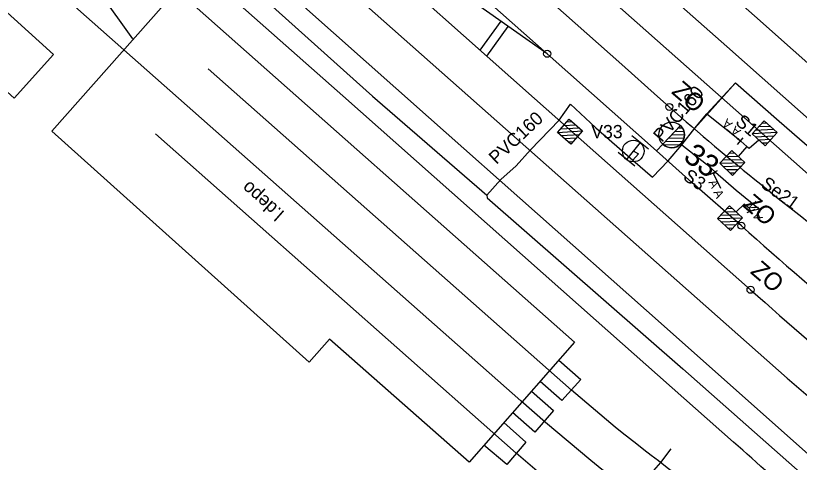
# Model space of a CAD drawing. Extents: x -496570 to -495506, y -1089156 to -1088046.
# Drawn here: x -496185.7 to -496096.7, y -1088542 to -1088491.2 of the extents above; entities that cross this region are included whole.
import ezdxf

# ---------------------------------------------------------------- set-up
doc = ezdxf.new("R2010")
doc.units = 0
for name, color, linetype in [('11', 7, 'Continuous'), ('14', 7, 'Continuous'), ('15', 7, 'Continuous'), ('20', 7, 'Continuous'), ('27', 7, 'Continuous'), ('39', 7, 'Continuous'), ('49', 7, 'Continuous'), ('54', 7, 'Continuous'), ('PŮVODNÍ_NÁVRH', 7, 'Continuous')]:
    doc.layers.add(name, color=color, linetype=linetype)

msp = doc.modelspace()

# ---------------------------------------------------------------- linework, layer by layer
at = {"layer": '11'}
for points in [[(-496132.942, -1088495.161), (-496130.564, -1088491.871)], [(-496132.204, -1088495.847), (-496129.754, -1088492.457)]]:
    msp.add_lwpolyline(points, dxfattribs=at)
at = {"layer": '14'}
for points in [[(-496500.326, -1088150.883), (-496478.319, -1088170.391), (-496459.205, -1088187.309), (-496440.603, -1088203.768), (-496419.398, -1088222.532), (-496401.337, -1088238.524), (-496381.863, -1088255.763), (-496363.496, -1088272.022), (-496344.908, -1088288.479), (-496325.602, -1088305.577), (-496305.115, -1088323.698), (-496285.279, -1088341.274), (-496267.778, -1088356.78), (-496248.642, -1088373.733), (-496220.391, -1088398.759), (-496201.351, -1088415.62), (-496182.974, -1088431.889), (-496164.259, -1088448.462), (-496145.687, -1088464.902), (-496132.984, -1088476.226), (-496115.09, -1088492.058), (-496092.682, -1088511.89), (-496073.961, -1088528.378)], [(-496111.45, -1088501.61), (-496112.796, -1088500.414), (-496116.847, -1088496.777), (-496137.726, -1088478.277), (-496158.004, -1088460.314), (-496179.39, -1088441.364), (-496198.571, -1088424.361), (-496223.52, -1088402.267), (-496247.329, -1088381.198), (-496269.626, -1088361.454), (-496288.304, -1088344.927), (-496319.947, -1088316.905), (-496344.485, -1088295.207), (-496348.139, -1088291.966), (-496366.841, -1088275.405), (-496385.169, -1088259.187), (-496404.395, -1088242.153), (-496422.154, -1088226.434), (-496443.818, -1088207.26), (-496462.548, -1088190.678), (-496481.576, -1088173.849), (-496503.417, -1088154.088)], [(-496036.118, -1088555.5), (-496048.975, -1088544.1), (-496066.196, -1088528.906), (-496086.152, -1088511.349), (-496104.929, -1088494.746), (-496123.588, -1088478.229), (-496142.293, -1088461.701), (-496160.965, -1088445.175), (-496179.891, -1088428.396), (-496198.214, -1088412.189), (-496217.292, -1088395.311), (-496245.811, -1088370.064), (-496264.918, -1088353.145), (-496281.988, -1088338.018), (-496302.247, -1088320.079), (-496322.57, -1088302.076), (-496341.966, -1088284.907), (-496360.552, -1088268.447), (-496378.713, -1088252.378), (-496398.4, -1088234.928), (-496416.447, -1088218.945), (-496437.668, -1088200.162), (-496456.103, -1088183.845), (-496474.042, -1088168.071)], [(-496419.776, -1088210.17), (-496413.73, -1088215.561), (-496395.384, -1088231.799), (-496375.938, -1088249.024), (-496357.661, -1088265.193), (-496339.088, -1088281.642), (-496320.817, -1088297.785), (-496278.447, -1088335.251), (-496262.212, -1088349.594), (-496242.734, -1088366.795), (-496214.147, -1088392.048), (-496195.339, -1088408.643), (-496176.8, -1088425.002), (-496157.997, -1088441.59), (-496139.148, -1088458.239), (-496120.509, -1088474.69), (-496101.775, -1088491.246), (-496088.913, -1088502.664), (-496081.326, -1088509.353), (-496072.768, -1088516.905)], [(-496183.115, -1088457.032), (-496166.27, -1088472.019), (-496131.046, -1088503.215), (-496098.048, -1088532.397), (-496093.805, -1088536.044)], [(-496093.621, -1088542.853), (-496114.06, -1088524.717), (-496138.8, -1088502.766), (-496174.593, -1088471.013)], [(-496173.425, -1088495.115), (-496178.653, -1088490.5), (-496194.892, -1088476.055)], [(-496147.947, -1088481.853), (-496126.772, -1088500.653), (-496102.22, -1088522.373)], [(-496104.138, -1088539.66), (-496119.75, -1088525.847), (-496148.539, -1088500.347), (-496166.679, -1088484.292)], [(-496128.341, -1088534.994), (-496173.425, -1088495.115)], [(-496125.191, -1088531.455), (-496163.844, -1088497.265)], [(-496131.495, -1088538.579), (-496169.855, -1088504.648)], [(-496103.261, -1088515.098), (-496108.88, -1088510.183), (-496112.903, -1088506.6)], [(-496117.617, -1088537.987), (-496122.554, -1088533.775), (-496125.191, -1088531.455)], [(-496120.36, -1088541.773), (-496125.528, -1088537.441), (-496128.341, -1088534.994)], [(-496084.463, -1088574.911), (-496099.443, -1088563.786), (-496104.369, -1088560.115), (-496107.079, -1088558.115), (-496114.808, -1088552.356), (-496123.542, -1088545.463), (-496128.839, -1088540.929), (-496131.495, -1088538.579)]]:
    msp.add_lwpolyline(points, dxfattribs=at)
for centre in [(-496111.45, -1088501.61), (-496103.261, -1088515.098), (-496102.22, -1088522.373)]:
    msp.add_circle(centre, 0.4, dxfattribs=at)
for centre, major_axis, ratio, start_param, end_param in [((-495904.217, -1088267.163), (240.608, -200.87), 0.998317, 4.684202, 4.771008), ((-495616.903, -1087969.14), (-563.673, 468.202), 0.997828, 1.536282, 1.586227), ((-495661.207, -1088025.176), (-508.889, 430.705), 0.996869, 1.547662, 1.600405)]:
    msp.add_ellipse(centre, major_axis=major_axis, ratio=ratio, start_param=start_param, end_param=end_param, dxfattribs=at)
for points in [[(-496060.305, -1088494.392), (-496069.107, -1088478.342), (-496082.819, -1088457.845), (-496098.833, -1088439.695), (-496101.304, -1088437.234), (-496120.979, -1088419.513)], [(-496076.529, -1088566.028), (-496092.943, -1088555.668), (-496104.359, -1088548.012), (-496117.617, -1088537.987)], [(-496076.075, -1088564.025), (-496087.586, -1088554.298), (-496104.138, -1088539.66)], [(-496063.641, -1088579.453), (-496076.368, -1088572.308), (-496088.307, -1088565.016), (-496095.758, -1088560.128), (-496107.252, -1088552.116), (-496120.36, -1088541.773)]]:
    msp.add_spline(points, degree=3, dxfattribs=at)
at = {"layer": '15'}
for p, q in [((-496123.441, -1088503.711), (-496122.116, -1088503.63)), ((-496123.09, -1088503.314), (-496122.513, -1088503.278)), ((-496099.993, -1088503.816), (-496101.319, -1088503.882)), ((-496100.386, -1088503.461), (-496100.964, -1088503.489)), ((-496124.144, -1088504.505), (-496121.321, -1088504.333)), ((-496123.793, -1088504.108), (-496121.718, -1088503.981)), ((-496123.747, -1088504.856), (-496121.672, -1088504.73)), ((-496099.206, -1088504.528), (-496102.031, -1088504.669)), ((-496099.599, -1088504.173), (-496101.676, -1088504.276)), ((-496123.35, -1088505.208), (-496122.024, -1088505.127)), ((-496122.953, -1088505.559), (-496122.375, -1088505.524)), ((-496114.768, -1088505.65), (-496116.312, -1088507.57)), ((-496113.808, -1088506.422), (-496115.728, -1088504.878)), ((-496099.562, -1088504.921), (-496101.638, -1088505.025)), ((-496099.918, -1088505.315), (-496101.245, -1088505.381)), ((-496100.274, -1088505.708), (-496100.852, -1088505.737)), ((-496115.352, -1088508.342), (-496117.272, -1088506.798)), ((-496104.982, -1088507.233), (-496103.654, -1088507.198)), ((-496104.617, -1088506.848), (-496104.039, -1088506.833)), ((-496105.712, -1088508.003), (-496102.885, -1088507.928)), ((-496105.347, -1088507.618), (-496103.269, -1088507.563)), ((-496105.328, -1088508.367), (-496103.249, -1088508.313)), ((-496104.942, -1088508.733), (-496103.615, -1088508.698)), ((-496104.558, -1088509.098), (-496103.98, -1088509.082)), ((-496105.242, -1088513.516), (-496103.915, -1088513.468)), ((-496104.881, -1088513.128), (-496104.303, -1088513.107)), ((-496105.965, -1088514.293), (-496103.138, -1088514.191)), ((-496105.604, -1088513.905), (-496103.526, -1088513.83)), ((-496105.577, -1088514.654), (-496103.499, -1088514.579)), ((-496105.188, -1088515.015), (-496103.861, -1088514.968)), ((-496104.8, -1088515.377), (-496104.222, -1088515.356))]:
    msp.add_line(p, q, dxfattribs=at)
for points in [[(-496122.819, -1088503.007), (-496121.321, -1088504.333), (-496122.646, -1088505.83), (-496124.144, -1088504.505)], [(-496122.819, -1088503.007), (-496121.321, -1088504.333), (-496122.646, -1088505.83), (-496124.144, -1088504.505)], [(-496100.549, -1088506.011), (-496102.031, -1088504.669), (-496100.689, -1088503.186), (-496099.206, -1088504.528)], [(-496100.549, -1088506.011), (-496102.031, -1088504.669), (-496100.689, -1088503.186), (-496099.206, -1088504.528)], [(-496104.335, -1088506.552), (-496102.885, -1088507.928), (-496104.261, -1088509.379), (-496105.712, -1088508.003)], [(-496104.335, -1088506.552), (-496102.885, -1088507.928), (-496104.261, -1088509.379), (-496105.712, -1088508.003)], [(-496104.602, -1088512.829), (-496103.138, -1088514.191), (-496104.501, -1088515.655), (-496105.965, -1088514.293)], [(-496104.602, -1088512.829), (-496103.138, -1088514.191), (-496104.501, -1088515.655), (-496105.965, -1088514.293)]]:
    msp.add_lwpolyline(points, close=True, dxfattribs=at)
for points in [[(-496122.819, -1088503.007), (-496121.321, -1088504.333), (-496122.646, -1088505.83), (-496124.144, -1088504.505), (-496122.819, -1088503.007)], [(-496122.819, -1088503.007), (-496121.321, -1088504.333), (-496122.646, -1088505.83), (-496124.144, -1088504.505), (-496122.819, -1088503.007)], [(-496100.549, -1088506.011), (-496102.031, -1088504.669), (-496100.689, -1088503.186), (-496099.206, -1088504.528), (-496100.549, -1088506.011)], [(-496100.549, -1088506.011), (-496102.031, -1088504.669), (-496100.689, -1088503.186), (-496099.206, -1088504.528), (-496100.549, -1088506.011)], [(-496104.335, -1088506.552), (-496102.885, -1088507.928), (-496104.261, -1088509.379), (-496105.712, -1088508.003), (-496104.335, -1088506.552)], [(-496104.335, -1088506.552), (-496102.885, -1088507.928), (-496104.261, -1088509.379), (-496105.712, -1088508.003), (-496104.335, -1088506.552)], [(-496104.602, -1088512.829), (-496103.138, -1088514.191), (-496104.501, -1088515.655), (-496105.965, -1088514.293), (-496104.602, -1088512.829)], [(-496104.602, -1088512.829), (-496103.138, -1088514.191), (-496104.501, -1088515.655), (-496105.965, -1088514.293), (-496104.602, -1088512.829)]]:
    msp.add_lwpolyline(points, dxfattribs=at)
msp.add_circle((-496115.542, -1088506.615), 1.232, dxfattribs=at)
at = {"layer": '20'}
for p, q in [((-496104.858, -1088504.172), (-496103.38, -1088505.49)), ((-496103.713, -1088505.863), (-496103.047, -1088505.117)), ((-496106, -1088508.882), (-496106.9, -1088509.318)), ((-496105.586, -1088510.881), (-496106.45, -1088509.1)), ((-496101.719, -1088513.247), (-496102.641, -1088513.633))]:
    msp.add_line(p, q, dxfattribs=at)
at = {"layer": '27'}
for p, q in [((-496112.198, -1088505.85), (-496110.187, -1088503.724)), ((-496110.187, -1088503.724), (-496112.198, -1088505.851)), ((-496111.177, -1088504.771), (-496109.734, -1088504.73)), ((-496110.813, -1088504.386), (-496109.798, -1088504.357)), ((-496110.448, -1088504), (-496109.972, -1088503.986)), ((-496111.906, -1088505.541), (-496109.909, -1088505.485)), ((-496111.542, -1088505.156), (-496109.767, -1088505.106)), ((-496112.199, -1088505.851), (-496112.903, -1088506.6)), ((-496112.198, -1088505.851), (-496112.198, -1088505.85)), ((-496112.111, -1088505.922), (-496110.213, -1088505.869))]:
    msp.add_line(p, q, dxfattribs=at)
for points in [[(-496112.903, -1088506.6), (-496125.331, -1088495.572), (-496137.6, -1088484.685)], [(-496125.331, -1088495.572), (-496138.739, -1088486.107)]]:
    msp.add_lwpolyline(points, dxfattribs=at)
for centre, radius in [((-496125.331, -1088495.572), 0.4), ((-496111.186, -1088504.782), 1.462)]:
    msp.add_circle(centre, radius, dxfattribs=at)
msp.add_arc((-496111.193, -1088504.787), 1.464, 226.63601, 46.59686, dxfattribs=at)
at = {"layer": '39'}
for points in [[(-496181.425, -1088495.664), (-496185.899, -1088500.598), (-496230.62, -1088460.017), (-496226.16, -1088455.098), (-496181.425, -1088495.664)], [(-496172.423, -1088493.891), (-496176.128, -1088488.669), (-496172.468, -1088484.41), (-496167.748, -1088488.466)], [(-496122.209, -1088528.323), (-496134.209, -1088541.938), (-496150.053, -1088527.973), (-496152.367, -1088530.599), (-496181.619, -1088504.378), (-496167.429, -1088488.299), (-496122.209, -1088528.323)]]:
    msp.add_lwpolyline(points, dxfattribs=at)
at = {"layer": '49'}
for points in [[(-496124.001, -1088530.356), (-496121.516, -1088532.546), (-496123.672, -1088534.964), (-496126.143, -1088532.786)], [(-496127.121, -1088533.896), (-496124.62, -1088536.1), (-496126.735, -1088538.543), (-496129.257, -1088536.32)], [(-496130.254, -1088537.45), (-496127.744, -1088539.662), (-496129.927, -1088542.223), (-496132.529, -1088540.032)]]:
    msp.add_lwpolyline(points, dxfattribs=at)
at = {"layer": '54'}
for p, q in [((-496103.68, -1088505.2), (-496103.38, -1088505.49)), ((-496102.63, -1088506.12), (-496103.61, -1088507.24))]:
    msp.add_line(p, q, dxfattribs=at)
for points in [[(-496165.07, -1088482.9), (-496156.87, -1088489.91), (-496145.17, -1088500.37), (-496132.17, -1088511.64), (-496132.14, -1088511.95), (-496109.93, -1088531.36), (-496085.16, -1088553.21), (-496080.73, -1088556.99), (-496073.59, -1088563.01), (-496067.7, -1088567.42), (-496060.271, -1088572.567), (-496056.99, -1088574.85), (-496054.978, -1088576.218), (-496044.9, -1088583.07), (-496037.32, -1088587.86), (-496035.7, -1088586.08), (-496034.22, -1088583.93), (-496031.57, -1088584.92), (-496029.17, -1088586.56)], [(-496132.17, -1088511.64), (-496130.59, -1088509.85), (-496128.84, -1088508.31), (-496127.24, -1088506.49), (-496123.97, -1088503.13), (-496122.68, -1088501.29), (-496120.41, -1088503.4), (-496119.8, -1088504), (-496115.587, -1088507.663), (-496113.37, -1088509.59), (-496111.59, -1088507.72), (-496110.03, -1088505.93), (-496108.55, -1088504.03), (-496107.19, -1088502.41), (-496103.923, -1088498.868), (-496098.957, -1088503.214), (-496092.024, -1088509.261)], [(-496107.19, -1088502.41), (-496103.68, -1088505.2), (-496102.63, -1088506.12), (-496102.39, -1088506.29), (-496101.29, -1088505.34)], [(-496115.54, -1088506.61), (-496114.97, -1088506.95), (-496115.587, -1088507.663)], [(-496110.03, -1088505.93), (-496107.21, -1088508.11), (-496106.204, -1088509.002), (-496103.87, -1088511.07), (-496101.2, -1088513.21), (-496102.18, -1088513.44), (-496102.35, -1088513.13), (-496102.94, -1088512.64), (-496103.87, -1088513.51)], [(-496106.45, -1088509.1), (-496106.29, -1088509.09), (-496106.204, -1088509.002)]]:
    msp.add_lwpolyline(points, dxfattribs=at)
at = {"layer": 'PŮVODNÍ_NÁVRH'}
for points in [[(-496113.37, -1088509.59), (-496111.59, -1088507.72), (-496110.03, -1088505.93), (-496108.55, -1088504.03), (-496103.923, -1088498.868)], [(-496132.17, -1088511.64), (-496130.59, -1088509.85), (-496128.84, -1088508.31), (-496127.24, -1088506.49), (-496123.97, -1088503.13), (-496122.68, -1088501.29)], [(-496122.394, -1088552.331), (-496118.881, -1088549.335), (-496115.606, -1088545.612), (-496112.41, -1088541.972), (-496111.251, -1088540.429)]]:
    msp.add_lwpolyline(points, dxfattribs=at)

# ---------------------------------------------------------------- texts
at = {"layer": '14'}
for p in [(-496111.305, -1088499.998), (-496103.225, -1088512.834), (-496102.344, -1088520.419)]:
    msp.add_text('ZO', height=2, rotation=319.41817, dxfattribs=at).set_placement(p)
at = {"layer": '15'}
msp.add_text('V33', height=1.5, dxfattribs=at).set_placement((-496120.322, -1088505.159))
at = {"layer": '20'}
for s, height, rotation, p in [('  A A', 1, 138.28218, (-496102.7, -1088504.792)), ('S1', 1.5, 319.5893, (-496104.049, -1088503.466)), ('S3', 1.5, 325.07278, (-496110, -1088509.769)), ('  A A', 1, 295.87718, (-496107.345, -1088509.486)), ('Se21', 1.5, 324.44231, (-496101.181, -1088510.624)), ('  A A', 1, 112.8226, (-496100.491, -1088514.919))]:
    msp.add_text(s, height=height, rotation=rotation, dxfattribs=at).set_placement(p)
at = {"layer": '27'}
msp.add_text('33', height=2.5, rotation=323.28202, dxfattribs=at).set_placement((-496109.983, -1088507.548))
at = {"layer": '39'}
msp.add_text('l.depo', height=1.5, rotation=138.60685, dxfattribs=at).set_placement((-496155.12, -1088513.541))
at = {"layer": '54'}
for rotation, p in [(49.41794, (-496112.287, -1088505.702)), (43.33753, (-496131.099, -1088508.214))]:
    msp.add_text('PVC160', height=1.5, rotation=rotation, dxfattribs=at).set_placement(p)

doc.saveas('drawing.dxf')
